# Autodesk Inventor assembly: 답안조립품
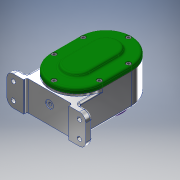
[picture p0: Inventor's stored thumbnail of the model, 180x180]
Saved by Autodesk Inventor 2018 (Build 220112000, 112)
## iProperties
Created: 2021-05
Part Number: 답안조립품
Material: 일반
Document SubType Name: Assembly
Designer: admin
Author: admin
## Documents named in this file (19)
- C:\Users\admin\Desktop\710509V1012\답안조립품.iam
- C:\Users\admin\Desktop\710509V1012\본체.ipt
- C:\Users\admin\Desktop\710509V1012\축 A.ipt
- C:\Users\admin\Desktop\710509V1012\커버 A.ipt
- C:\Users\admin\Desktop\710509V1012\베어링 6002.ipt
- 베어링 6002.ipt
- C:\Users\admin\Desktop\710509V1012\베어링 6001.ipt
- 베어링 6001.ipt
- C:\Users\admin\Desktop\710509V1012\칼라.ipt
- C:\Users\admin\Desktop\710509V1012\축 B.ipt
- C:\Users\admin\Desktop\710509V1012\키 5 x 5 x 12.ipt
- C:\Users\admin\Desktop\710509V1012\스퍼기어 A.ipt
- C:\Users\admin\Desktop\710509V1012\키 4 x 4 x 12.ipt
- C:\Users\admin\Desktop\710509V1012\스퍼기어 B.ipt
- C:\Users\admin\Desktop\710509V1012\개스킷 A.ipt
- C:\Users\admin\Desktop\710509V1012\개스킷 B.ipt
- C:\Users\admin\Desktop\710509V1012\커버 B.ipt
- C:\Users\admin\Desktop\710509V1012\오일 실 12 22 7.ipt
- C:\Users\admin\Desktop\710509V1012\볼트 M4.ipt
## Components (2 placed, 2 different names)
1. 개스킷 A:1
2. 개스킷 B:1
